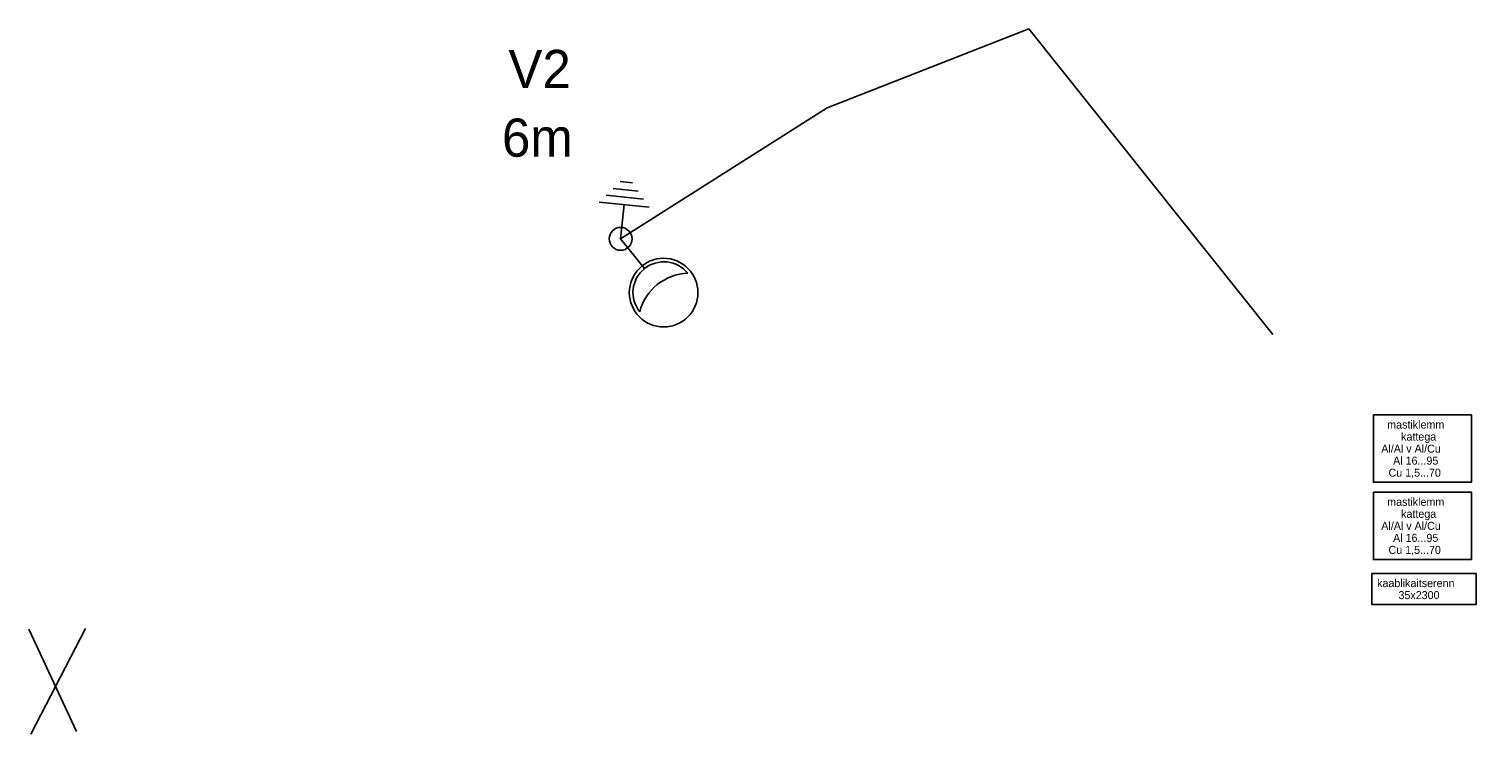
# Model space of a CAD drawing. Extents: x 554241.6 to 554320, y 6593498.2 to 6593528.9.
# Drawn here: x 554282.06 to 554320.03, y 6593510.41 to 6593528.89 of the extents above; entities that cross this region are included whole.
import ezdxf

# ---------------------------------------------------------------- set-up
doc = ezdxf.new("R2010")
doc.units = 0
for name, color, linetype in [('LIKV', 7, 'Continuous'), ('TELG', 7, 'Continuous'), ('V KAABEL TORUS 75mm 450N', 7, 'Continuous'), ('V LIKV', 7, 'Continuous'), ('V MAANDUS', 7, 'Continuous'), ('V MAST 6m', 7, 'Continuous'), ('V TXT', 7, 'Continuous')]:
    doc.layers.add(name, color=color, linetype=linetype)

msp = doc.modelspace()

# ---------------------------------------------------------------- linework, layer by layer
at = {"layer": 'LIKV'}
for points in [[(554317.337, 6593518.774), (554319.908, 6593518.774), (554319.908, 6593517.008), (554317.337, 6593517.008)], [(554317.337, 6593516.751), (554319.908, 6593516.751), (554319.908, 6593514.984), (554317.337, 6593514.984)], [(554317.299, 6593514.615), (554320.029, 6593514.615), (554320.029, 6593513.802), (554317.299, 6593513.802)]]:
    msp.add_lwpolyline(points, close=True, dxfattribs=at)
at = {"layer": 'TELG'}
msp.add_line((554297.585, 6593523.39), (554298.211, 6593522.61), dxfattribs=at)
msp.add_circle((554298.714, 6593521.98), 0.9, dxfattribs=at)
for centre, radius, start, end in [((554298.717, 6593521.981), 0.807, 128.7536, 218.7536), ((554298.717, 6593521.981), 0.807, 38.7536, 128.7536), ((554299.391, 6593521.141), 1.346, 91.8837, 165.6235)]:
    msp.add_arc(centre, radius, start, end, dxfattribs=at)
at = {"layer": 'V KAABEL TORUS 75mm 450N'}
msp.add_lwpolyline([(554297.585, 6593523.39), (554303.008, 6593526.826), (554308.292, 6593528.891), (554314.701, 6593520.885)], dxfattribs=at)
at = {"layer": 'V LIKV'}
for p, q in [((554282.062, 6593513.156), (554283.311, 6593510.472)), ((554282.114, 6593510.41), (554283.542, 6593513.174))]:
    msp.add_line(p, q, dxfattribs=at)
at = {"layer": 'V MAANDUS'}
for p, q in [((554297.901, 6593524.855), (554297.574, 6593524.889)), ((554298.189, 6593524.432), (554297.207, 6593524.533)), ((554298.045, 6593524.644), (554297.39, 6593524.711)), ((554298.332, 6593524.22), (554297.023, 6593524.355)), ((554297.585, 6593523.39), (554297.678, 6593524.287))]:
    msp.add_line(p, q, dxfattribs=at)
at = {"layer": 'V MAST 6m'}
msp.add_line((554297.585, 6593523.39), (554297.585, 6593523.39), dxfattribs=at)
msp.add_circle((554297.585, 6593523.39), 0.3, dxfattribs=at)

# ---------------------------------------------------------------- texts
at = {"layer": 'LIKV'}
for s, p in [('mastiklemm', (554317.698, 6593518.416)), ('Al/Al v Al/Cu', (554317.543, 6593517.786)), ('kattega', (554318.063, 6593518.101)), ('Al 16...95', (554317.853, 6593517.471)), ('Cu 1,5...70', (554317.733, 6593517.156)), ('mastiklemm', (554317.698, 6593516.392)), ('kattega', (554318.063, 6593516.077)), ('Al/Al v Al/Cu', (554317.543, 6593515.762)), ('Cu 1,5...70', (554317.733, 6593515.132)), ('Al 16...95', (554317.853, 6593515.447)), ('kaablikaitserenn', (554317.434, 6593514.261)), ('35x2300', (554317.994, 6593513.946))]:
    msp.add_text(s, height=0.21, dxfattribs=at).set_placement(p)
at = {"layer": 'V TXT'}
for s, p in [('V2', (554294.642, 6593527.343)), ('6m', (554294.473, 6593525.543))]:
    msp.add_text(s, height=1, dxfattribs=at).set_placement(p)

doc.saveas('drawing.dxf')
